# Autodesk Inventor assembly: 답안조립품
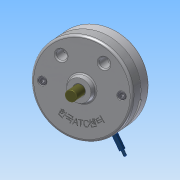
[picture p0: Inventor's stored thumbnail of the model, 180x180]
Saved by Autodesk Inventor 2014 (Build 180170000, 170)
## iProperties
Created: 2015-06
Part Number: 답안조립품
Document SubType Name: Assembly
Designer: Administrator
Author: Administrator
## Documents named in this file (10)
- C:\Documents and Settings\Administrator\바탕 화면\450631V1022\답안조립품.iam
- C:\Documents and Settings\Administrator\바탕 화면\450631V1022\1-본체.ipt
- C:\Documents and Settings\Administrator\바탕 화면\450631V1022\덮개.ipt
- C:\Documents and Settings\Administrator\바탕 화면\450631V1022\축.ipt
- C:\Documents and Settings\Administrator\바탕 화면\450631V1022\멈춤링.ipt
- C:\Documents and Settings\Administrator\바탕 화면\450631V1022\베어링62_22.ipt
- C:\Documents and Settings\Administrator\바탕 화면\450631V1022\슬라이더2.ipt
- C:\Documents and Settings\Administrator\바탕 화면\450631V1022\평행핀.ipt
- C:\Documents and Settings\Administrator\바탕 화면\450631V1022\슬라이더.ipt
- C:\Documents and Settings\Administrator\바탕 화면\450631V1022\M10x35.ipt
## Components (8 placed, 5 different names)
1. 1-본체:1
2. KS B 1336 22 x 1.2:1
3. KS B 1336 22 x 1.2:2
4. KS B 2023 62/22 - 22 x 50 x 14:1
5. KS B 2023 62/22 - 22 x 50 x 14:2
6. KS B 1320 B B 5 x  20:1
7. KS B 1003 - 미터 M 10 x 35:1
8. KS B 1003 - 미터 M 10 x 35:2
